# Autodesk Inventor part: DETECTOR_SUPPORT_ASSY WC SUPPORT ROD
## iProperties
Shininess: 64.0
Length Units: 11272
Angle Units: 11279
Time Units: 11290
Mass Units: 11286
Length Display Precision: 3
Angle Display Precision: 2
Compacted: True
Part Number: DETECTOR_SUPPORT_ASSY WC SUPPORT ROD
Document SubType Name: Modeling
Created: 2004-08
Designer: John Blackburn
Material: ALUMINUM
Manufacturer: Standard
Standards Organization: Custom
Density: 0.0
Volumn: 0.0
Area: 0.0
PropertySet Name: Model Information
Control State: 0
Master: False
Checked Out: False
Author: John Blackburn
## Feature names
1. ExtrusionBlind1
2. ExtrusionBlind2
3. Chamfer1
